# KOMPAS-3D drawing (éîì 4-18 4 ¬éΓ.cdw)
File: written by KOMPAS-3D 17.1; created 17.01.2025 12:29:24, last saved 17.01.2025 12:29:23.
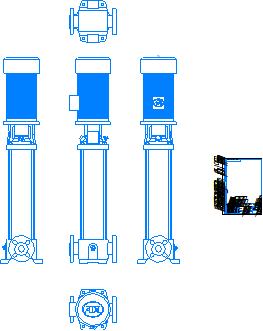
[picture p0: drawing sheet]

Sheet 1: A4, portrait

Title block, sheet 1: name: ВМН 4-18 4 кВт; designation: ВМН 4-18 4 кВт; material: Сталь 10  ГОСТ 1050-2013; mass: 53,1; sheets: 1; sheet format: A4; stored path: \\adlc.lan\data\АДЛ_ПКД\3D-модели\ADL production\Насосы ГРАНПАМП\Насосы ВМН\ВМН4\KOMPAS 3D\ВМН 4-18 4 кВт.cdw

Views: Вид 1, Спереди, Проекционный вид 2, Проекционный вид 3, Проекционный вид 4, Проекционный вид 5
Referenced files in \\adlc.lan\data\АДЛ_ПКД\3D-модели\ADL production\Насосы ГРАНПАМП\Насосы ВМН\ВМН4\KOMPAS 3D\: ВМН 4-18 4 кВт.m3d
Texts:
  Andrey
  АДЛ
Dimensions and other numbers on the sheet: 1:1; 1; 53,1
